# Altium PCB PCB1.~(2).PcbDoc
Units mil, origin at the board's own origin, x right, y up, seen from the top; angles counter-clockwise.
Board outline 1610.59 x 1610.59 mil, 2 copper layers (Top Layer, Bottom Layer); 25 components, 8 nets, 53 pads, 0 vias.
Unrouted connection lines stored in the file: 45.
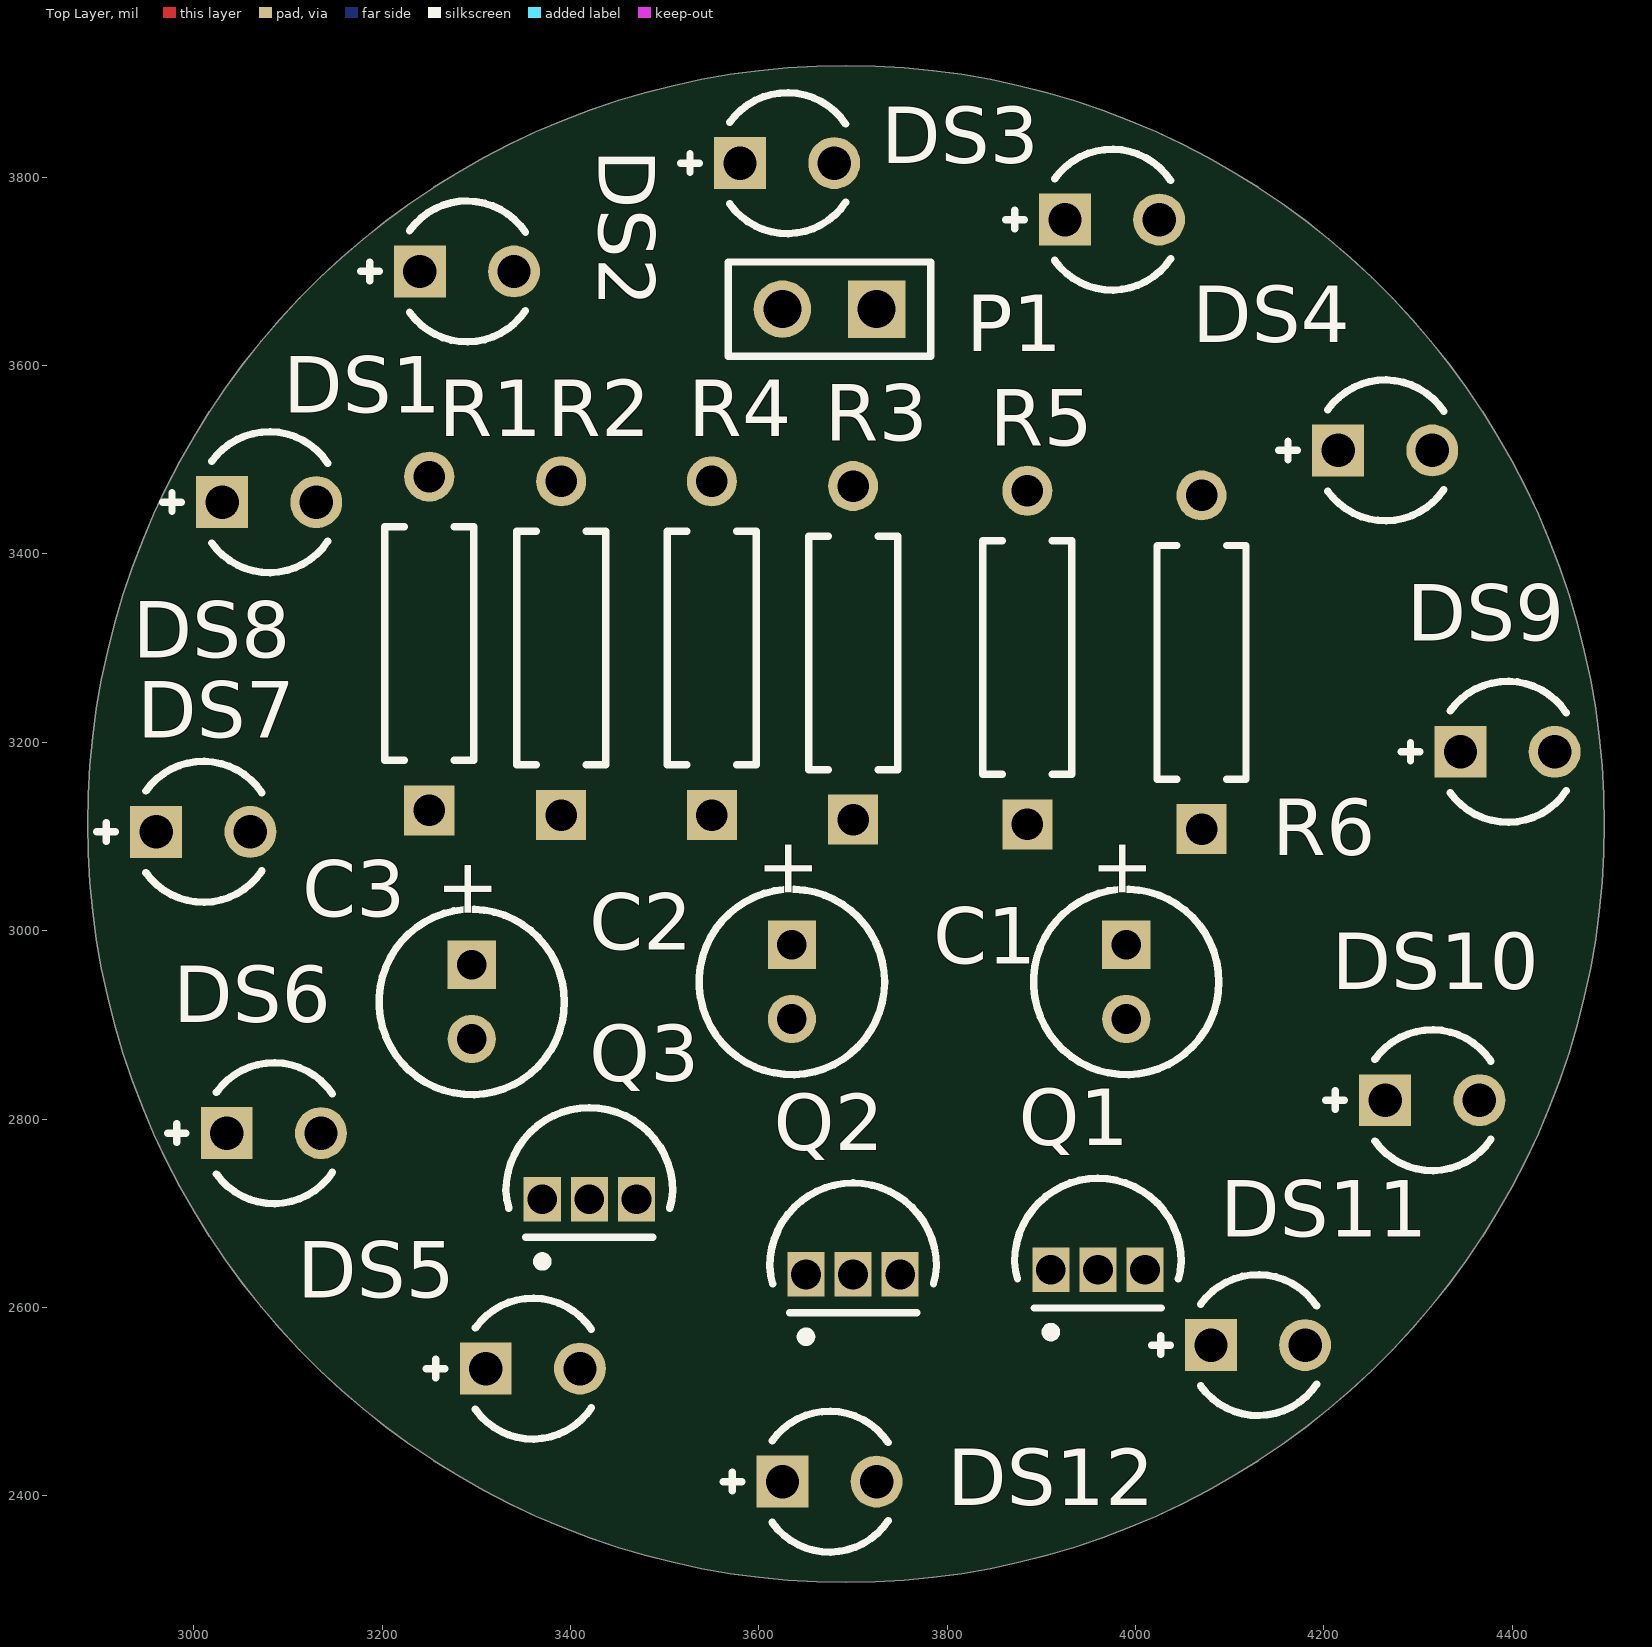
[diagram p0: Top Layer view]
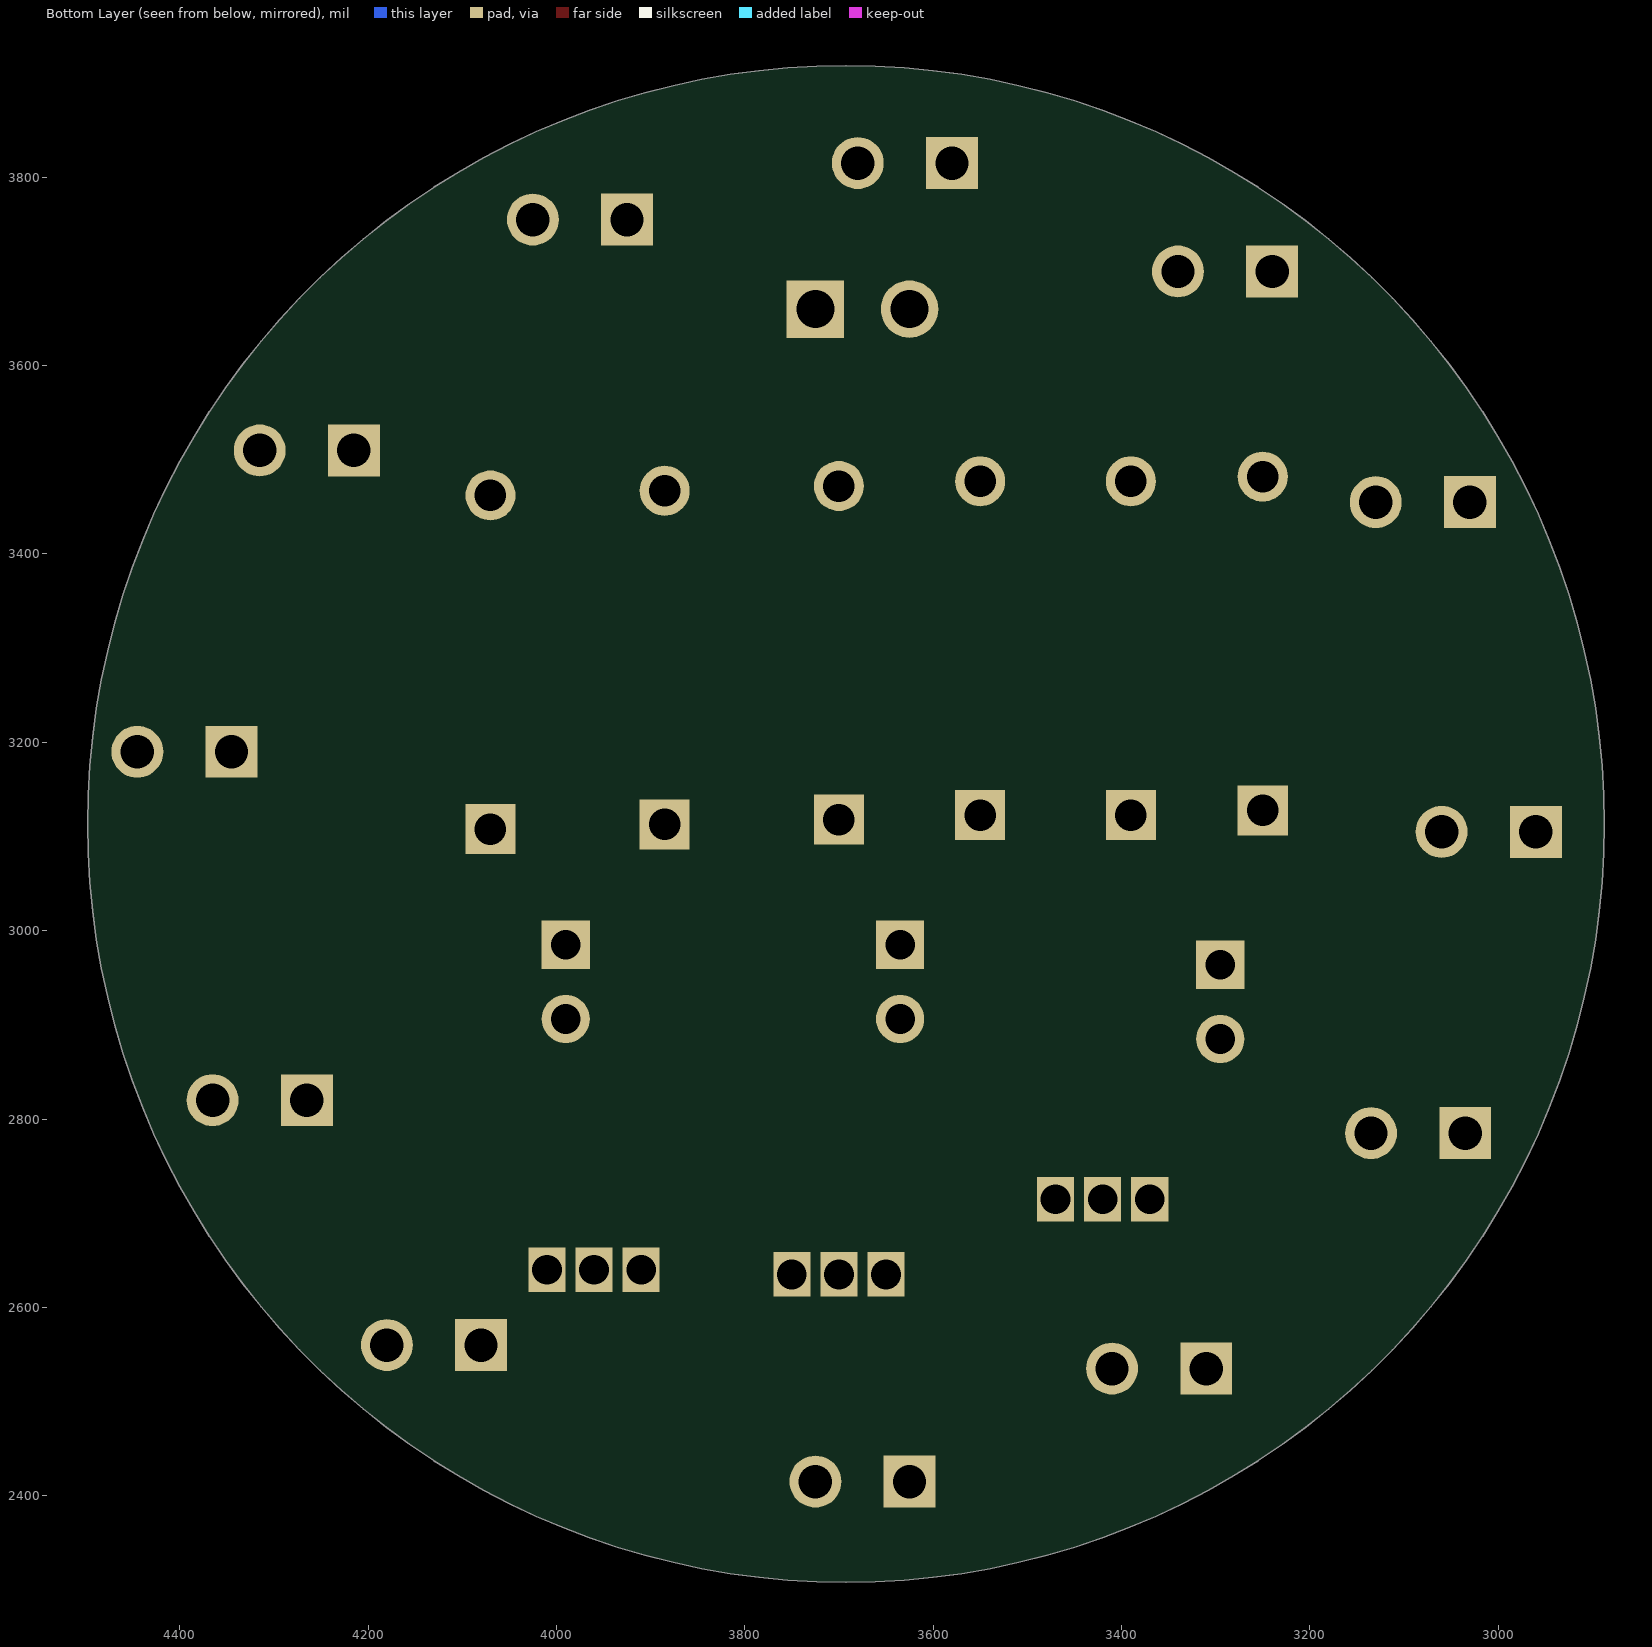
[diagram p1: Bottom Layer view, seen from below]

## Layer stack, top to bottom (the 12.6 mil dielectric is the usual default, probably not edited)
Top Solder: solder mask 0.4, Solder Resist, Dk 3.5
Top Layer: signal copper 1.4
Dielectric 1: dielectric 12.6, FR-4, Dk 4.8
Bottom Layer: signal copper 1.4
Bottom Solder: solder mask 0.4, Solder Resist, Dk 3.5

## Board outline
2887.19,3113.29 ccw(c3692.49,3113.29) 3692.49,2307.99 ccw(c3692.49,3113.29) 4497.78,3113.29 ccw(c3692.49,3113.29) 3692.49,3918.58 ccw(c3692.49,3113.29)

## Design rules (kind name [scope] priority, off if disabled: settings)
Clearance [All] p1: gap=10 ignorepadtopadclearanceinfootprint=FALSE
PolygonConnect [All] p1: connectstyle=Relief reliefconductorwidth=10 reliefentries=4 polygonreliefangle="90 Angle" airgapwidth=10
RoutingVias [All] p1: holewidth=28 width=50 viastyle="Through Hole" minholewidth=28 minwidth=50 maxholewidth=28 maxwidth=50
SolderMaskExpansion [All] p1: expansion=4 istentingtop=FALSE
Width [All] p1: maxlimit=10 minlimit=10 preferedwidth=10
30 further rules are at their usual default settings.

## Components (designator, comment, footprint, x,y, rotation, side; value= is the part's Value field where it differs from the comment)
C1 "ECA1HM220" CAPPR55-200-1100X500X1200 3990,2945.63 r270 top value=22µF
C2 "ECA1HM220" CAPPR55-200-1100X500X1200 3635,2945.63 r270 top value=22µF
C3 "ECA1HM220" CAPPR55-200-1100X500X1200 3295,2924.37 r270 top value=22µF
DS1 "LTL-1CHE" INDPR60-254-520X380X650 3290,3700 r0 top
DS2 "LTL-1CHE" INDPR60-254-520X380X650 3630,3815 r0 top
DS3 "LTL-1CHE" INDPR60-254-520X380X650 3975,3755 r0 top
DS4 "LTL-1CHE" INDPR60-254-520X380X650 4265,3510 r0 top
DS5 "LTL-1CHE" INDPR60-254-520X380X650 3360,2535 r0 top
DS6 "LTL-1CHE" INDPR60-254-520X380X650 3085,2785 r0 top
DS7 "LTL-1CHE" INDPR60-254-520X380X650 3010,3105 r0 top
DS8 "LTL-1CHE" INDPR60-254-520X380X650 3080,3455 r0 top
DS9 "LTL-1CHE" INDPR60-254-520X380X650 4395,3190 r0 top
DS10 "LTL-1CHE" INDPR60-254-520X380X650 4315,2820 r0 top
DS11 "LTL-1CHE" INDPR60-254-520X380X650 4130,2560 r0 top
DS12 "LTL-1CHE" INDPR60-254-520X380X650 3675,2415 r0 top
P1 "TSW-102-26-F-S" SMTC-TSW-102-26-XX-S 3725,3660 r180 top
Q1 "S9013" JSCJ-TO-92-3_V 3960,2640 r0 top
Q2 "S9013" JSCJ-TO-92-3_V 3700,2635 r0 top
Q3 "S9013" JSCJ-TO-92-3_V 3420,2715 r0 top
R1 "MFR-25FBF52-10K" RESA60-630X240 3250,3305 r90 top value=10k
R2 "MFR-25FBF52-10K" RESA60-630X240 3390,3300 r90 top value=10k
R3 "MFR-25FBF52-10K" RESA60-630X240 3700,3295 r90 top value=10k
R4 "MFR-25FBF52-10K" RESA60-630X240 3550,3300 r90 top value=330R
R5 "" RESA60-630X240 3885,3290 r90 top value=330R
R6 "330R" RESA60-630X240 4070,3285 r90 top

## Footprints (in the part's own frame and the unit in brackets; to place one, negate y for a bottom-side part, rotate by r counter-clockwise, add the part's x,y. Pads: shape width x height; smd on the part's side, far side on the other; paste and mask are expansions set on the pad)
CAPPR55-200-1100X500X1200 [mm] "THD, 2-Leads, Dia 5mm, Pin Spacing 2mm"
  rect 1.3x1.3 hole 0.8: 1(-1,0)
  round 1.3 hole 0.8: 2(1,0)
  silkscreen extent -2.5,-2.5 2.5,2.5, body extent -2.5,-2.5 2.45,2.5, height 12
INDPR60-254-520X380X650 [mm] "THD, 2-Leads, Dia 3.8mm, Pitch 2.54mm"
  rect 1.4x1.4 hole 0.9: 1(-1.27,0)
  round 1.4 hole 0.9: 2(1.27,0)
  silkscreen extent -2.87,-1.9 1.58,1.9, body extent -1.9,-1.9 1.9,1.9, height 6.5
JSCJ-TO-92-3_V [mm] "TO-92, 3-leads, Height 4.7mm, Pitch 1.27mm"
  rect 1x1.2 hole 0.8: 1(-1.27,0) 2(0,0) 3(1.27,0)
  silkscreen extent -2.25,-1.81 2.25,2.47, body extent -2.25,-1.03 2.25,2.47, height 4.7
RESA60-630X240 [mm] "Axial Resistor, 2-Leads, Dia 2.4mm, Body Length 6.3mm"
  rect 1.35x1.35 hole 0.85: 1(-4.5,0)
  round 1.35 hole 0.85: 2(4.5,0)
  silkscreen extent -3.15,-1.2 3.15,1.2, body extent -4.77,-1.19 4.77,1.2, height 2.4
SMTC-TSW-102-26-XX-S [mm] ".025 SQ Post Terminal Strip Assembly, 1x2 Pins, Vertical, 2.54mm Pitch, Male"
  rect 1.55x1.55 hole 1.02: 1(0,0)
  round 1.55 hole 1.02: 2(2.54,0)
  silkscreen extent -1.46,-1.27 4,1.27, body extent -1.4,-1.27 3.81,1.27, height 8.38

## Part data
C1 C2 C3: library part CMP-001-00027-7, "Aluminum Electrolytic Capacitor, 22 uF, +/- 20%, 50 V, -40 to 85 degC, 2-Pin THD, RoHS, Bulk", Capacitor Type=Electrolytic, Case/Package=Radial, Manufacturer=Panasonic, Max Operating Temperature=85°C, Min Operating Temperature=-40°C, Package Description="2-Pin Radial Lead, Dia 5 mm, Height 12 mm", Package Quantity=200, Package Reference=CAPPR55-200-1100X500X1200, Ripple Current=100mA, Tolerance=20%, Voltage Rating=50V
DS1 DS2 DS3 DS4 DS5 DS6 DS7 DS8 DS9 DS10 DS11 DS12: library part CMP-007-00018-2, "LED Uni-Color Red, 100 mW, 30 mA, -55 to 100 degC, 2-Pin THD, RoHS, Bulk", Case/Package=Radial, Colour=Red, Forward Current=20mA, Forward Voltage=2V, Manufacturer=Lite-On, Max Operating Temperature=100°C, Min Operating Temperature=-55°C, Package Description="2-Pin Through Hole Device, Dia 3.8 mm, Pitch 2.54 mm", Package Quantity=1000
P1: library part CMP-1024-00329-1, "0.025\" SQ Post Header, Through-hole, Vertical, -55 to 125 degC, 2.54 mm Pitch, 2-Pin, Male, RoHS", Manufacturer=Samtec, Temperature Range="-55 to 125 degC"
Q1 Q2 Q3: library part CMP-013-00000-3, "Transistor, NPN, 0.1 uA, 150 MHz, 3-Pin TO-92", Case/Package=TO-92-3, Manufacturer="Jiangsu Changjiang Electronics Technology", Package Description="3-Pin Through Hole Device, Height 4.7 mm, Pitch 2.3 mm"
R1 R2 R3 R4 R5 R6: library part CMP-009-00047-4, "Axial Resistor, 10 KOhm, +/- 1%, 0.25 W, -55 to 155 degC, 2-Pin THD, RoHS, Bulk", Case/Package=Axial, Manufacturer=Yageo, Max Operating Temperature=155°C, Min Operating Temperature=-55°C, Package Description="2-Pin Axial Lead, Dia 2.4 mm, Body Length 6.3 mm", Package Quantity=200, Package Reference=MFR-25, Power=250mW, Tolerance=1%, Voltage Rating=250V

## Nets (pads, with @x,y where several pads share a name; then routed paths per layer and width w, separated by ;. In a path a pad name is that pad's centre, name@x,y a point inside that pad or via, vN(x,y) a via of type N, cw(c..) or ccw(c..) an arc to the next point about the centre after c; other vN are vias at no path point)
NetC1_1: C1.1 Q2.2 R3.1
NetC1_2: C1.2 DS1.1 DS2.1 DS3.1 DS4.1 Q1.3 R4.1
NetC2_1: C2.1 Q3.2 R2.1
NetC2_2: C2.2 DS5.1 DS6.1 DS7.1 DS8.1 Q2.3 R5.1
NetC3_1: C3.1 Q1.2 R1.1
NetC3_2: C3.2 DS9.1 DS10.1 DS11.1 DS12.1 Q3.3 R6.1
NetDS1_2: DS1.2 DS2.2 DS3.2 DS4.2 DS5.2 DS6.2 DS7.2 DS8.2 DS9.2 DS10.2 DS11.2 DS12.2 P1.2 Q1.1 Q2.1 Q3.1
NetP1_1: P1.1 R1.2 R2.2 R3.2 R4.2 R5.2 R6.2

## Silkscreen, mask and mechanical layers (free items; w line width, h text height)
Mechanical 1:
  circle w10: c3692.49,3113.29 r805.29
